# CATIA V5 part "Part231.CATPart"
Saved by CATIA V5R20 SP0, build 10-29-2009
Part number: DFA 168700-1
Revision: ANY
Definition: UNKNOWN
Nomenclature: DFA 168700-1
Source: Unknown
Bounding box of the stored display mesh (mm): x -3.804 to 3.804, y 0.28 to 2.5, z -4 to 4
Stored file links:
  C:\Users\Utente\Desktop\IO LAVORO\3D X SITO CF\CUMSA\3D files FA\FA 200712-21\Part231.CATPart
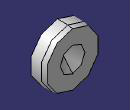
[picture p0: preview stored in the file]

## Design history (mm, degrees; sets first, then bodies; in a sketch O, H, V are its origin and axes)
Body1 "Cortar-Extruir1" (main body)
  Solid1: solid without history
